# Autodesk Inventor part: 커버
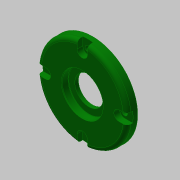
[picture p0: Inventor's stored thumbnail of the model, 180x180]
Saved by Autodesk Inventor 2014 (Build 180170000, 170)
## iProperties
Created: 2020-05
Part Number: 커버
Material: 알루미늄 6061
Document SubType Name: Modeling
Designer: mduedu
Density: 1 g/cm^3
Appearance: 진녹색
Author: mduedu
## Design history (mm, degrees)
sketch "스케치1"
  geometry: L1 (0, 0)-(8, 0); L2 (8, 0)-(8, 35); L3 (8, 35)-(0, 35); L4 (0, 35)-(0, 0); L5 (8, 0)-(12, 0); L6 (12, 0)-(12, 23.5); L7 (12, 23.5)-(8, 23.5); L8 (8, 23.5)-(8, 0)
  constraints: 16 end point, 4 parallel, 2 horizontal, 2 perpendicular
  dimensions: "d0" = 70 diameter of L3 L1; "d2" = 47 diameter of L7 L5; "d3" = 4 distance of L6.end L7.end; "d4" = 12 distance between parallel lines of L4 L6
revolve "회전1" sketch "스케치1" stored, may be unused: angle "d5" = 90 deg
hole "구멍1" diameter "d8" = 22; stored, may be unused: countersink angle "d12" = 90 deg, drill point angle "d14" = 118 deg; dims "d6" = 10, "d7" = 10, "d9" = 6, "d10" = 32, "d11" = 5.2, "d13" = 8
hole "구멍2" diameter "d17" = 40; stored, may be unused: countersink angle "d21" = 90 deg, drill point angle "d23" = 0 deg; dims "d15" = 10, "d16" = 10, "d18" = 6, "d19" = 32, "d20" = 5.2, "d22" = 4
fillet "모깎기1" dims "d24" = 3
fillet "모깎기2" dims "d25" = 3
fillet "모깎기3" dims "d26" = 0.3
chamfer "모따기1" distance "d27" = 0.5; stored, may be unused: second distance "d28" = 2, angle "d29" = 30 deg
chamfer "모따기2" distance "d30" = 1; stored, may be unused: second distance "d31" = 2, angle "d32" = 30 deg
sketch "스케치2" dims "d33" = 57
  geometry: L1 (-4, 28.5)-(4, 28.5); L2 (4, 28.5)-(4, 38.5); L3 (4, 38.5)-(-4, 38.5); L4 (-4, 38.5)-(-4, 28.5); 4 further points
  constraints: 8 end point, 2 horizontal alignment, 2 midpoint, 2 parallel, 2 vertical alignment, 1 coincident, 1 horizontal, 1 perpendicular, 6 other
  dimensions: "d34" = 8 distance between parallel lines of L2 L4; "d35" = 10 distance of point (0, 28.5) point (0, 38.5)
extrude "돌출1" cut sketch "스케치2" distance "d36" = 4.4; taper "d37" = 0 deg
sketch "스케치3"
  geometry: A1 r 4 centre (0, 28.5) between (-4, 28.5) and (4, 28.5) reference; 2 further points
  constraints: 1 coincident
hole "구멍3" sketch "스케치3" at (0, 28.5) diameter "d38" = 4.5; stored, may be unused: countersink angle "d42" = 90 deg, drill point angle "d44" = 0 deg; dims "d39" = 6, "d40" = 32, "d41" = 5.2, "d43" = 4
node "솔리드1"
pattern_circular "원형 패턴1" dims angle "d46" = 360 deg
